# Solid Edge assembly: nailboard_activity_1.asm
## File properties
Author: conerly
Template: ansi assembly.asm
Last saved by: jccrumbl
Revision: 90
Application: Solid Edge
Revision: 1
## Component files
Board.psm
Cable tie.par
14Pin.par
8PinRound.par
8PinSquare.par
3PinLongConnector.par
4PinConnector.par
5PinRoundConnector.par
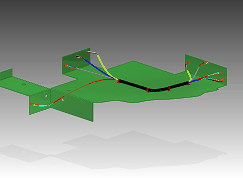
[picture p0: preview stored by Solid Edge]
